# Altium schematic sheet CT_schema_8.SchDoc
size 254 x 194 mm
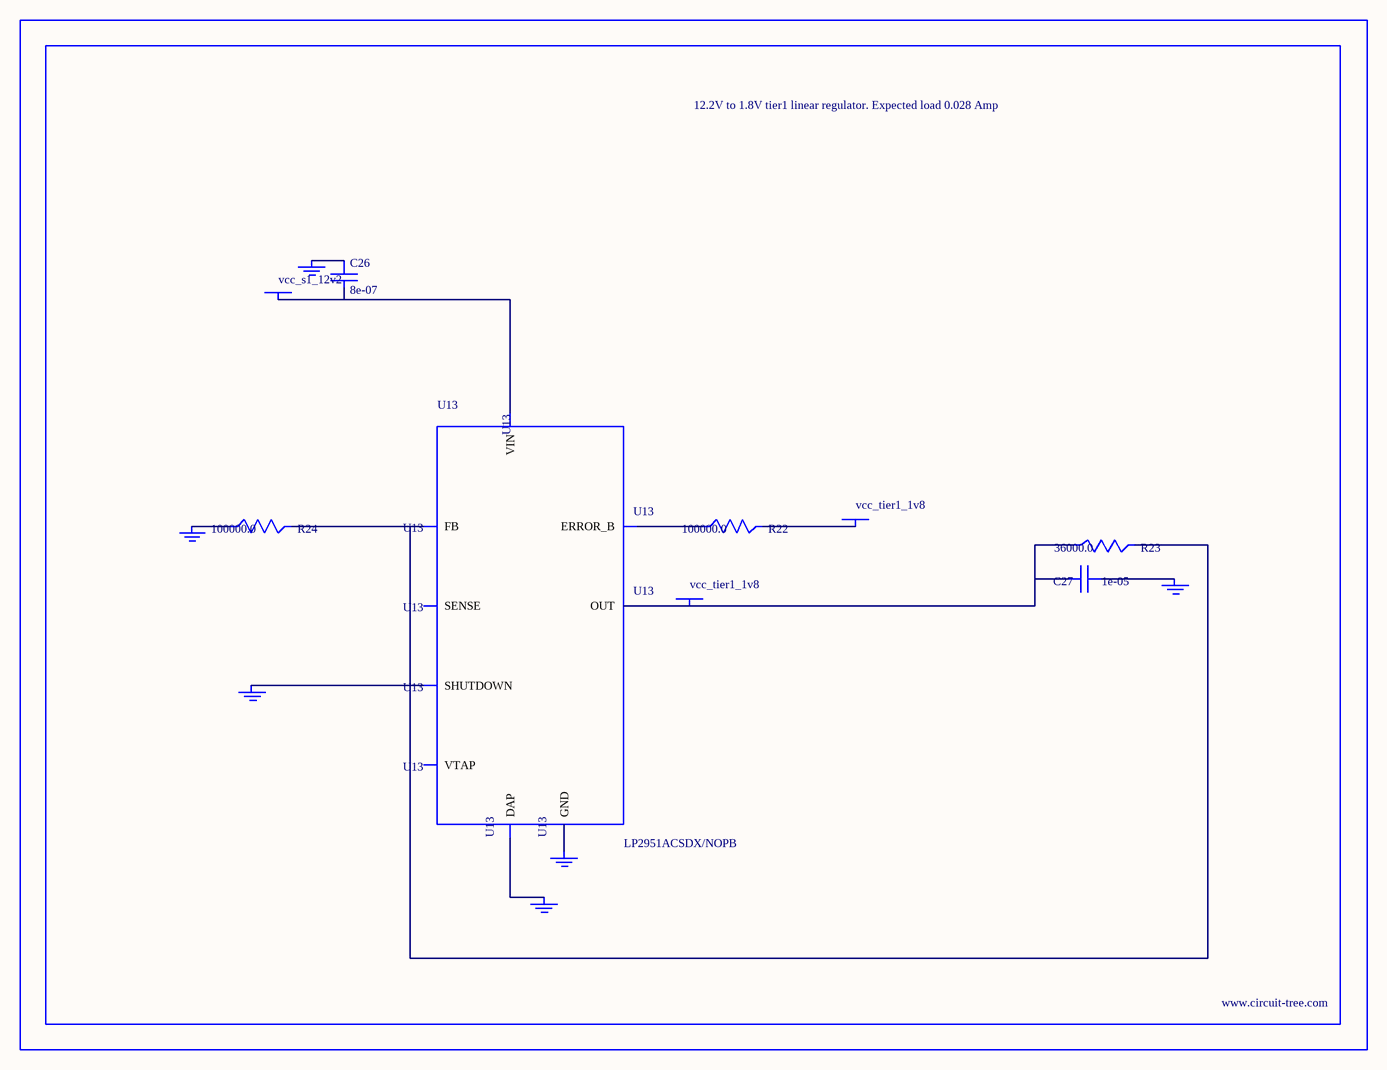
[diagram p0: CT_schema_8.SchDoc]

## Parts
BORDER7  (no value)
C26  8e-07  [R0603]
C27  1e-05  [C0805]
GND_INSTANCE_7_0  (no value)
GND_INSTANCE_7_1  (no value)
GND_INSTANCE_7_2  (no value)
GND_INSTANCE_7_3  (no value)
GND_INSTANCE_7_4  (no value)
GND_INSTANCE_7_5  (no value)
POWER_INSTANCE_7_0  vcc_tier1_1v8
POWER_INSTANCE_7_1  vcc_s1_12v2
POWER_INSTANCE_7_2  vcc_tier1_1v8
R22  100000.0  [R0603]
R23  36000.0  [R0603]
R24  100000.0  [R0603]
U13  LP2951ACSDX/NOPB  [WSON-8]

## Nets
NetC26_1: C26.1 GND_INSTANCE_7_3.0(GND)
NetC26_2: C26.2 POWER_INSTANCE_7_1.0(PWR) U13.8(VIN)
NetC27_1: C27.1 GND_INSTANCE_7_0.0(GND)
NetC27_2: C27.2 POWER_INSTANCE_7_2.0(PWR) R23.1 U13.1(OUT)
NetGND_INSTANCE_7_1_0: GND_INSTANCE_7_1.0(GND) U13.3(SHUTDOWN)
NetGND_INSTANCE_7_2_0: GND_INSTANCE_7_2.0(GND) R24.1
NetGND_INSTANCE_7_4_0: GND_INSTANCE_7_4.0(GND) U13.PAD(DAP)
NetGND_INSTANCE_7_5_0: GND_INSTANCE_7_5.0(GND) U13.4(GND)
NetPOWER_INSTANCE_7_0_0: POWER_INSTANCE_7_0.0(PWR) R22.2
NetR22_1: R22.1 U13.5(ERROR_B)
NetR23_2: R23.2 R24.2 U13.7(FB)

Not connected (* = marked no-connect by the designer): U13 2(SENSE) 6(VTAP)

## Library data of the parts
BORDER7 = BORDER_PAGE7
C26 = C26
C27 = GRM219R60J106ME19D
GND_INSTANCE_7_0-GND_INSTANCE_7_5 = GND
POWER_INSTANCE_7_0-POWER_INSTANCE_7_2 = PWR
R22 R24 = RC0603JR-07100KL
R23 = RC0603JR-0736KL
